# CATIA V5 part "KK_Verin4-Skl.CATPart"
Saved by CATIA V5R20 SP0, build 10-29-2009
Part number: Verin4-Skl
Bounding box of the stored display mesh (mm): x 43.513 to 50.294, y -86.432 to -47.974, z 0 to 100
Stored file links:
  G:\Khaled_CFAO_2011\ST2M\ST2M_GR1\msallin\Khaled\Version_Finale\KK_Verin4-Skl.CATPart
  C:\Users\Mathieu\Desktop\Think Motion\JOUG-MELEE2.CATProduct
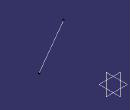
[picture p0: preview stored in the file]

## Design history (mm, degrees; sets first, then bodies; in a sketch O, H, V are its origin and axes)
Set1
  Point1: linked copy from another document
  Point2: linked copy from another document
Set2
  Line1: type PtPt, FirstPoint Point1, SecondPoint Point2
Body1 (main body)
